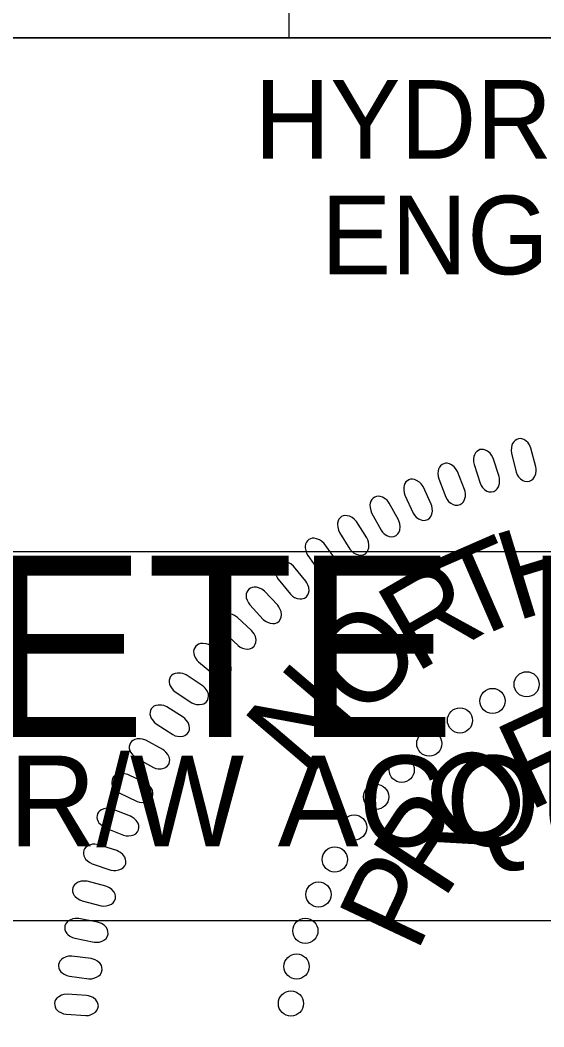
# Model space of a CAD drawing. Extents: x 505692 to 527456, y 415959 to 439886.
# Drawn here: x 507266.6 to 507299.9, y 439748.2 to 439812.2 of the extents above; entities that cross this region are included whole.
import ezdxf

# ---------------------------------------------------------------- set-up
doc = ezdxf.new("R2010")
doc.units = 0
for name, color, linetype in [('Sheet PE Seal Cell', 7, 'Continuous'), ('Sheet Profile CELL', 7, 'Continuous'), ('Sheet Sticker Incomplete CELL', 7, 'Continuous')]:
    doc.layers.add(name, color=color, linetype=linetype)

msp = doc.modelspace()

# ---------------------------------------------------------------- linework, layer by layer
at = {"layer": 'Sheet PE Seal Cell'}
for points in [[(507299.392, 439783.818), (507299.088, 439785.006), (507298.997, 439785.209), (507298.912, 439785.332), (507298.761, 439785.468), (507298.64, 439785.55), (507298.512, 439785.599), (507298.4, 439785.613), (507298.286, 439785.604), (507298.183, 439785.557), (507298.075, 439785.498), (507297.988, 439785.414), (507297.911, 439785.291), (507297.873, 439785.199), (507297.845, 439785.037), (507297.832, 439784.849), (507297.849, 439784.689), (507298.155, 439783.47), (507298.218, 439783.311), (507298.297, 439783.187), (507298.423, 439783.054), (507298.566, 439782.947), (507298.68, 439782.894), (507298.848, 439782.874), (507298.997, 439782.893), (507299.132, 439782.968), (507299.221, 439783.042), (507299.319, 439783.171), (507299.393, 439783.365), (507299.414, 439783.556), (507299.41, 439783.688)], [(507297.059, 439783.197), (507296.68, 439784.364), (507296.577, 439784.561), (507296.484, 439784.677), (507296.326, 439784.804), (507296.199, 439784.879), (507296.068, 439784.92), (507295.956, 439784.926), (507295.843, 439784.91), (507295.742, 439784.857), (507295.639, 439784.791), (507295.557, 439784.702), (507295.488, 439784.575), (507295.456, 439784.48), (507295.438, 439784.317), (507295.437, 439784.128), (507295.464, 439783.969), (507295.845, 439782.772), (507295.919, 439782.618), (507296.005, 439782.499), (507296.139, 439782.374), (507296.289, 439782.276), (507296.406, 439782.23), (507296.574, 439782.222), (507296.722, 439782.249), (507296.852, 439782.333), (507296.937, 439782.413), (507297.027, 439782.547), (507297.088, 439782.745), (507297.096, 439782.937), (507297.085, 439783.069)], [(507294.858, 439782.381), (507294.407, 439783.521), (507294.291, 439783.712), (507294.192, 439783.822), (507294.025, 439783.939), (507293.894, 439784.005), (507293.761, 439784.038), (507293.649, 439784.037), (507293.537, 439784.013), (507293.44, 439783.954), (507293.34, 439783.882), (507293.264, 439783.788), (507293.204, 439783.657), (507293.178, 439783.561), (507293.17, 439783.397), (507293.181, 439783.208), (507293.218, 439783.051), (507293.674, 439781.88), (507293.757, 439781.731), (507293.85, 439781.617), (507293.992, 439781.502), (507294.147, 439781.413), (507294.267, 439781.374), (507294.436, 439781.377), (507294.582, 439781.414), (507294.706, 439781.506), (507294.785, 439781.59), (507294.867, 439781.73), (507294.916, 439781.931), (507294.912, 439782.123), (507294.892, 439782.255)], [(507292.741, 439781.448), (507292.219, 439782.558), (507292.092, 439782.74), (507291.985, 439782.845), (507291.812, 439782.951), (507291.677, 439783.008), (507291.541, 439783.033), (507291.43, 439783.024), (507291.32, 439782.995), (507291.227, 439782.929), (507291.131, 439782.851), (507291.062, 439782.753), (507291.009, 439782.618), (507290.99, 439782.52), (507290.992, 439782.356), (507291.015, 439782.168), (507291.062, 439782.014), (507291.59, 439780.874), (507291.682, 439780.73), (507291.783, 439780.623), (507291.932, 439780.517), (507292.093, 439780.438), (507292.214, 439780.407), (507292.382, 439780.42), (507292.526, 439780.465), (507292.644, 439780.565), (507292.717, 439780.655), (507292.79, 439780.799), (507292.826, 439781.003), (507292.811, 439781.194), (507292.783, 439781.324)], [(507290.658, 439780.434), (507290.067, 439781.509), (507289.929, 439781.684), (507289.816, 439781.781), (507289.636, 439781.875), (507289.498, 439781.925), (507289.361, 439781.941), (507289.251, 439781.925), (507289.142, 439781.889), (507289.054, 439781.818), (507288.963, 439781.734), (507288.9, 439781.631), (507288.857, 439781.493), (507288.843, 439781.394), (507288.855, 439781.231), (507288.89, 439781.044), (507288.947, 439780.894), (507289.545, 439779.789), (507289.646, 439779.651), (507289.753, 439779.55), (507289.908, 439779.454), (507290.074, 439779.385), (507290.197, 439779.362), (507290.364, 439779.385), (507290.504, 439779.44), (507290.616, 439779.546), (507290.684, 439779.64), (507290.748, 439779.789), (507290.77, 439779.995), (507290.743, 439780.185), (507290.707, 439780.313)], [(507288.64, 439779.292), (507287.983, 439780.328), (507287.834, 439780.493), (507287.716, 439780.583), (507287.53, 439780.667), (507287.389, 439780.707), (507287.252, 439780.714), (507287.142, 439780.692), (507287.037, 439780.648), (507286.952, 439780.572), (507286.868, 439780.482), (507286.811, 439780.376), (507286.776, 439780.236), (507286.768, 439780.136), (507286.792, 439779.974), (507286.838, 439779.79), (507286.904, 439779.643), (507287.571, 439778.578), (507287.68, 439778.447), (507287.793, 439778.353), (507287.954, 439778.266), (507288.123, 439778.209), (507288.248, 439778.193), (507288.413, 439778.227), (507288.55, 439778.29), (507288.655, 439778.403), (507288.717, 439778.502), (507288.771, 439778.654), (507288.781, 439778.861), (507288.741, 439779.049), (507288.697, 439779.174)], [(507286.64, 439777.937), (507285.919, 439778.93), (507285.76, 439779.086), (507285.636, 439779.168), (507285.445, 439779.239), (507285.302, 439779.271), (507285.165, 439779.269), (507285.056, 439779.24), (507284.954, 439779.19), (507284.875, 439779.109), (507284.796, 439779.014), (507284.746, 439778.904), (507284.72, 439778.762), (507284.718, 439778.662), (507284.752, 439778.501), (507284.809, 439778.321), (507284.885, 439778.179), (507285.617, 439777.158), (507285.735, 439777.034), (507285.853, 439776.947), (507286.019, 439776.87), (507286.192, 439776.823), (507286.318, 439776.816), (507286.48, 439776.86), (507286.612, 439776.932), (507286.71, 439777.052), (507286.765, 439777.153), (507286.81, 439777.309), (507286.807, 439777.516), (507286.756, 439777.701), (507286.704, 439777.824)], [(507284.759, 439776.548), (507283.977, 439777.494), (507283.809, 439777.639), (507283.68, 439777.713), (507283.485, 439777.772), (507283.341, 439777.795), (507283.203, 439777.785), (507283.097, 439777.749), (507282.998, 439777.693), (507282.924, 439777.606), (507282.852, 439777.507), (507282.808, 439777.394), (507282.792, 439777.25), (507282.796, 439777.151), (507282.84, 439776.992), (507282.908, 439776.816), (507282.993, 439776.678), (507283.787, 439775.706), (507283.913, 439775.589), (507284.036, 439775.51), (507284.207, 439775.445), (507284.382, 439775.409), (507284.508, 439775.409), (507284.667, 439775.463), (507284.795, 439775.543), (507284.884, 439775.669), (507284.934, 439775.774), (507284.968, 439775.931), (507284.952, 439776.138), (507284.889, 439776.319), (507284.83, 439776.439)], [(507282.972, 439775.009), (507282.132, 439775.904), (507281.955, 439776.038), (507281.821, 439776.105), (507281.623, 439776.151), (507281.478, 439776.165), (507281.341, 439776.146), (507281.237, 439776.104), (507281.142, 439776.042), (507281.074, 439775.95), (507281.007, 439775.846), (507280.971, 439775.731), (507280.964, 439775.587), (507280.974, 439775.488), (507281.028, 439775.333), (507281.107, 439775.161), (507281.199, 439775.03), (507282.055, 439774.108), (507282.187, 439773.999), (507282.315, 439773.929), (507282.489, 439773.874), (507282.667, 439773.848), (507282.793, 439773.856), (507282.948, 439773.92), (507283.071, 439774.008), (507283.152, 439774.14), (507283.195, 439774.248), (507283.219, 439774.407), (507283.191, 439774.612), (507283.116, 439774.79), (507283.05, 439774.904)], [(507281.309, 439773.4), (507280.415, 439774.24), (507280.23, 439774.363), (507280.092, 439774.42), (507279.892, 439774.455), (507279.745, 439774.459), (507279.61, 439774.432), (507279.51, 439774.383), (507279.418, 439774.315), (507279.356, 439774.22), (507279.296, 439774.112), (507279.268, 439773.995), (507279.269, 439773.85), (507279.286, 439773.752), (507279.349, 439773.6), (507279.439, 439773.434), (507279.539, 439773.308), (507280.45, 439772.442), (507280.589, 439772.343), (507280.722, 439772.28), (507280.9, 439772.236), (507281.078, 439772.222), (507281.203, 439772.238), (507281.354, 439772.311), (507281.471, 439772.407), (507281.544, 439772.543), (507281.579, 439772.653), (507281.594, 439772.815), (507281.552, 439773.018), (507281.467, 439773.19), (507281.393, 439773.3)], [(507279.696, 439771.613), (507278.751, 439772.395), (507278.558, 439772.506), (507278.417, 439772.555), (507278.215, 439772.577), (507278.069, 439772.572), (507277.936, 439772.536), (507277.839, 439772.481), (507277.751, 439772.407), (507277.695, 439772.309), (507277.643, 439772.197), (507277.621, 439772.079), (507277.632, 439771.934), (507277.655, 439771.837), (507277.727, 439771.69), (507277.827, 439771.529), (507277.936, 439771.411), (507278.899, 439770.604), (507279.044, 439770.512), (507279.18, 439770.458), (507279.36, 439770.426), (507279.539, 439770.423), (507279.663, 439770.448), (507279.809, 439770.53), (507279.919, 439770.632), (507279.984, 439770.773), (507280.012, 439770.885), (507280.017, 439771.047), (507279.962, 439771.247), (507279.867, 439771.413), (507279.786, 439771.519)], [(507278.171, 439769.911), (507277.141, 439770.577), (507276.936, 439770.664), (507276.791, 439770.696), (507276.587, 439770.694), (507276.443, 439770.672), (507276.315, 439770.621), (507276.225, 439770.555), (507276.147, 439770.471), (507276.103, 439770.366), (507276.064, 439770.25), (507276.056, 439770.129), (507276.084, 439769.987), (507276.118, 439769.894), (507276.207, 439769.756), (507276.326, 439769.608), (507276.447, 439769.503), (507277.499, 439768.815), (507277.653, 439768.741), (507277.795, 439768.704), (507277.978, 439768.692), (507278.155, 439768.711), (507278.275, 439768.749), (507278.411, 439768.849), (507278.508, 439768.963), (507278.556, 439769.11), (507278.571, 439769.225), (507278.557, 439769.386), (507278.479, 439769.578), (507278.365, 439769.732), (507278.272, 439769.828)], [(507276.957, 439767.888), (507275.922, 439768.545), (507275.716, 439768.632), (507275.571, 439768.663), (507275.367, 439768.659), (507275.222, 439768.636), (507275.095, 439768.584), (507275.005, 439768.517), (507274.928, 439768.433), (507274.885, 439768.327), (507274.846, 439768.21), (507274.84, 439768.09), (507274.869, 439767.948), (507274.904, 439767.855), (507274.994, 439767.717), (507275.113, 439767.571), (507275.236, 439767.467), (507276.293, 439766.787), (507276.448, 439766.715), (507276.59, 439766.678), (507276.773, 439766.668), (507276.951, 439766.688), (507277.07, 439766.727), (507277.205, 439766.828), (507277.302, 439766.943), (507277.348, 439767.09), (507277.362, 439767.206), (507277.346, 439767.367), (507277.267, 439767.558), (507277.152, 439767.711), (507277.058, 439767.806)], [(507275.654, 439765.839), (507274.578, 439766.43), (507274.369, 439766.503), (507274.221, 439766.525), (507274.018, 439766.508), (507273.875, 439766.476), (507273.751, 439766.417), (507273.666, 439766.344), (507273.594, 439766.255), (507273.558, 439766.147), (507273.526, 439766.028), (507273.528, 439765.908), (507273.565, 439765.768), (507273.606, 439765.677), (507273.705, 439765.546), (507273.833, 439765.407), (507273.963, 439765.31), (507275.06, 439764.698), (507275.219, 439764.636), (507275.363, 439764.608), (507275.546, 439764.61), (507275.723, 439764.641), (507275.839, 439764.688), (507275.968, 439764.796), (507276.057, 439764.918), (507276.094, 439765.068), (507276.101, 439765.183), (507276.075, 439765.343), (507275.984, 439765.529), (507275.859, 439765.675), (507275.76, 439765.763)], [(507274.545, 439763.715), (507273.435, 439764.238), (507273.22, 439764.298), (507273.072, 439764.31), (507272.871, 439764.281), (507272.73, 439764.239), (507272.61, 439764.172), (507272.529, 439764.094), (507272.464, 439764.001), (507272.434, 439763.891), (507272.41, 439763.77), (507272.419, 439763.651), (507272.465, 439763.513), (507272.512, 439763.425), (507272.619, 439763.3), (507272.756, 439763.169), (507272.89, 439763.081), (507274.025, 439762.539), (507274.187, 439762.487), (507274.332, 439762.469), (507274.515, 439762.482), (507274.689, 439762.524), (507274.802, 439762.577), (507274.924, 439762.694), (507275.005, 439762.821), (507275.032, 439762.973), (507275.032, 439763.089), (507274.996, 439763.246), (507274.894, 439763.427), (507274.76, 439763.564), (507274.655, 439763.646)], [(507273.605, 439761.596), (507272.465, 439762.048), (507272.247, 439762.094), (507272.098, 439762.097), (507271.899, 439762.055), (507271.761, 439762.005), (507271.646, 439761.93), (507271.571, 439761.847), (507271.51, 439761.751), (507271.488, 439761.639), (507271.472, 439761.517), (507271.488, 439761.398), (507271.543, 439761.264), (507271.595, 439761.179), (507271.709, 439761.061), (507271.854, 439760.94), (507271.994, 439760.86), (507273.159, 439760.39), (507273.325, 439760.349), (507273.472, 439760.339), (507273.653, 439760.363), (507273.824, 439760.416), (507273.934, 439760.477), (507274.048, 439760.601), (507274.121, 439760.732), (507274.139, 439760.886), (507274.131, 439761.002), (507274.086, 439761.157), (507273.972, 439761.33), (507273.829, 439761.459), (507273.72, 439761.535)], [(507272.73, 439759.407), (507271.563, 439759.786), (507271.343, 439759.818), (507271.193, 439759.812), (507270.998, 439759.758), (507270.863, 439759.699), (507270.753, 439759.617), (507270.683, 439759.531), (507270.629, 439759.43), (507270.614, 439759.317), (507270.605, 439759.194), (507270.629, 439759.077), (507270.691, 439758.946), (507270.749, 439758.864), (507270.871, 439758.754), (507271.023, 439758.642), (507271.168, 439758.571), (507272.36, 439758.175), (507272.528, 439758.144), (507272.675, 439758.144), (507272.855, 439758.179), (507273.022, 439758.243), (507273.128, 439758.31), (507273.234, 439758.441), (507273.299, 439758.577), (507273.307, 439758.732), (507273.292, 439758.846), (507273.237, 439758.999), (507273.112, 439759.165), (507272.962, 439759.284), (507272.848, 439759.353)], [(507272.025, 439757.151), (507270.837, 439757.457), (507270.615, 439757.475), (507270.467, 439757.46), (507270.275, 439757.393), (507270.144, 439757.326), (507270.039, 439757.238), (507269.974, 439757.146), (507269.927, 439757.042), (507269.918, 439756.929), (507269.918, 439756.805), (507269.949, 439756.689), (507270.02, 439756.563), (507270.082, 439756.485), (507270.211, 439756.383), (507270.37, 439756.281), (507270.518, 439756.219), (507271.734, 439755.899), (507271.904, 439755.878), (507272.05, 439755.887), (507272.227, 439755.934), (507272.39, 439756.008), (507272.491, 439756.082), (507272.589, 439756.219), (507272.645, 439756.359), (507272.643, 439756.514), (507272.621, 439756.628), (507272.556, 439756.776), (507272.422, 439756.933), (507272.265, 439757.043), (507272.146, 439757.104)], [(507271.514, 439754.856), (507270.309, 439755.086), (507270.087, 439755.09), (507269.939, 439755.066), (507269.751, 439754.987), (507269.626, 439754.912), (507269.526, 439754.817), (507269.468, 439754.722), (507269.427, 439754.616), (507269.426, 439754.502), (507269.433, 439754.379), (507269.471, 439754.265), (507269.55, 439754.143), (507269.617, 439754.069), (507269.751, 439753.975), (507269.917, 439753.882), (507270.069, 439753.831), (507271.302, 439753.587), (507271.473, 439753.578), (507271.618, 439753.596), (507271.792, 439753.654), (507271.95, 439753.737), (507272.046, 439753.818), (507272.135, 439753.961), (507272.183, 439754.104), (507272.171, 439754.259), (507272.142, 439754.371), (507272.068, 439754.514), (507271.924, 439754.664), (507271.76, 439754.763), (507271.638, 439754.817)], [(507271.094, 439752.541), (507269.876, 439752.695), (507269.654, 439752.686), (507269.509, 439752.652), (507269.327, 439752.562), (507269.205, 439752.48), (507269.112, 439752.378), (507269.06, 439752.279), (507269.026, 439752.17), (507269.032, 439752.057), (507269.046, 439751.934), (507269.092, 439751.823), (507269.179, 439751.707), (507269.25, 439751.637), (507269.39, 439751.552), (507269.56, 439751.47), (507269.716, 439751.427), (507270.962, 439751.262), (507271.133, 439751.263), (507271.277, 439751.29), (507271.446, 439751.359), (507271.599, 439751.453), (507271.69, 439751.54), (507271.769, 439751.687), (507271.808, 439751.834), (507271.787, 439751.986), (507271.751, 439752.097), (507271.668, 439752.235), (507271.514, 439752.375), (507271.345, 439752.465), (507271.22, 439752.51)], [(507270.807, 439750.197), (507269.583, 439750.275), (507269.361, 439750.251), (507269.218, 439750.208), (507269.042, 439750.107), (507268.926, 439750.017), (507268.84, 439749.91), (507268.793, 439749.808), (507268.766, 439749.697), (507268.78, 439749.584), (507268.802, 439749.463), (507268.855, 439749.355), (507268.948, 439749.244), (507269.024, 439749.179), (507269.169, 439749.103), (507269.344, 439749.032), (507269.502, 439748.999), (507270.756, 439748.912), (507270.926, 439748.924), (507271.068, 439748.96), (507271.233, 439749.04), (507271.38, 439749.142), (507271.466, 439749.234), (507271.535, 439749.387), (507271.564, 439749.536), (507271.534, 439749.687), (507271.491, 439749.795), (507271.4, 439749.928), (507271.238, 439750.058), (507271.063, 439750.137), (507270.935, 439750.174)]]:
    msp.add_lwpolyline(points, close=True, dxfattribs=at)
for centre in [(507298.813, 439769.983), (507296.639, 439768.923), (507294.568, 439767.688), (507292.617, 439766.215), (507290.864, 439764.542), (507289.232, 439762.83), (507287.837, 439760.878), (507286.603, 439758.847), (507285.567, 439756.617), (507284.73, 439754.306), (507284.172, 439752.036), (507283.813, 439749.685)]:
    msp.add_circle(centre, 0.801, dxfattribs=at)
at = {"layer": 'Sheet Profile CELL'}
msp.add_line((507283.678, 439836.094), (507283.678, 439811.094), dxfattribs=at)
for points in [[(507158.628, 439836.144), (507358.678, 439836.144), (507358.678, 439811.094), (507158.628, 439811.094)], [(507258.678, 439811.094), (507358.678, 439811.094), (507358.678, 439698.594), (507258.678, 439698.594)]]:
    msp.add_lwpolyline(points, close=True, dxfattribs=at)
at = {"layer": 'Sheet Sticker Incomplete CELL'}
msp.add_lwpolyline([(507185.195, 439754.938), (507185.195, 439778.438), (507332.195, 439778.438), (507332.195, 439754.938)], close=True, dxfattribs=at)

# ---------------------------------------------------------------- texts
at = {"layer": 'Sheet PE Seal Cell'}
for s, rotation, p in [('H', 17.05575, (507298.102, 439773.981)), ('T', 23.5451, (507294.923, 439772.571)), ('R', 30.03446, (507291.702, 439770.652)), ('O', 43.01317, (507288.227, 439767.624)), ('N', 49.50253, (507284.88, 439763.868)), ('F', 25.10842, (507298.909, 439761.873)), ('O', 40.98802, (507295.212, 439758.734)), ('R', 56.86761, (507293.498, 439756.188)), ('P', 64.80741, (507291.811, 439752.826))]:
    msp.add_text(s, height=5.669, rotation=rotation, dxfattribs=at).set_placement(p)
at = {"layer": 'Sheet Profile CELL'}
for s, p in [('HYDRAULICS', (507281.49, 439803.407)), ('ENGINEER', (507285.74, 439796.057))]:
    msp.add_text(s, height=5.0001, dxfattribs=at).set_placement(p)
at = {"layer": 'Sheet Sticker Incomplete CELL'}
for s, height, p in [('INCOMPLETE PLANS', 11.52, (507194.145, 439766.638)), ('DO NOT USE FOR R/W ACQUISITION', 5.76, (507197.395, 439759.688))]:
    msp.add_text(s, height=height, dxfattribs=at).set_placement(p)

doc.saveas('drawing.dxf')
